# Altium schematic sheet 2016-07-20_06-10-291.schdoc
size 274 x 137 mm; SheetNumber: 1; SheetTotal: 1
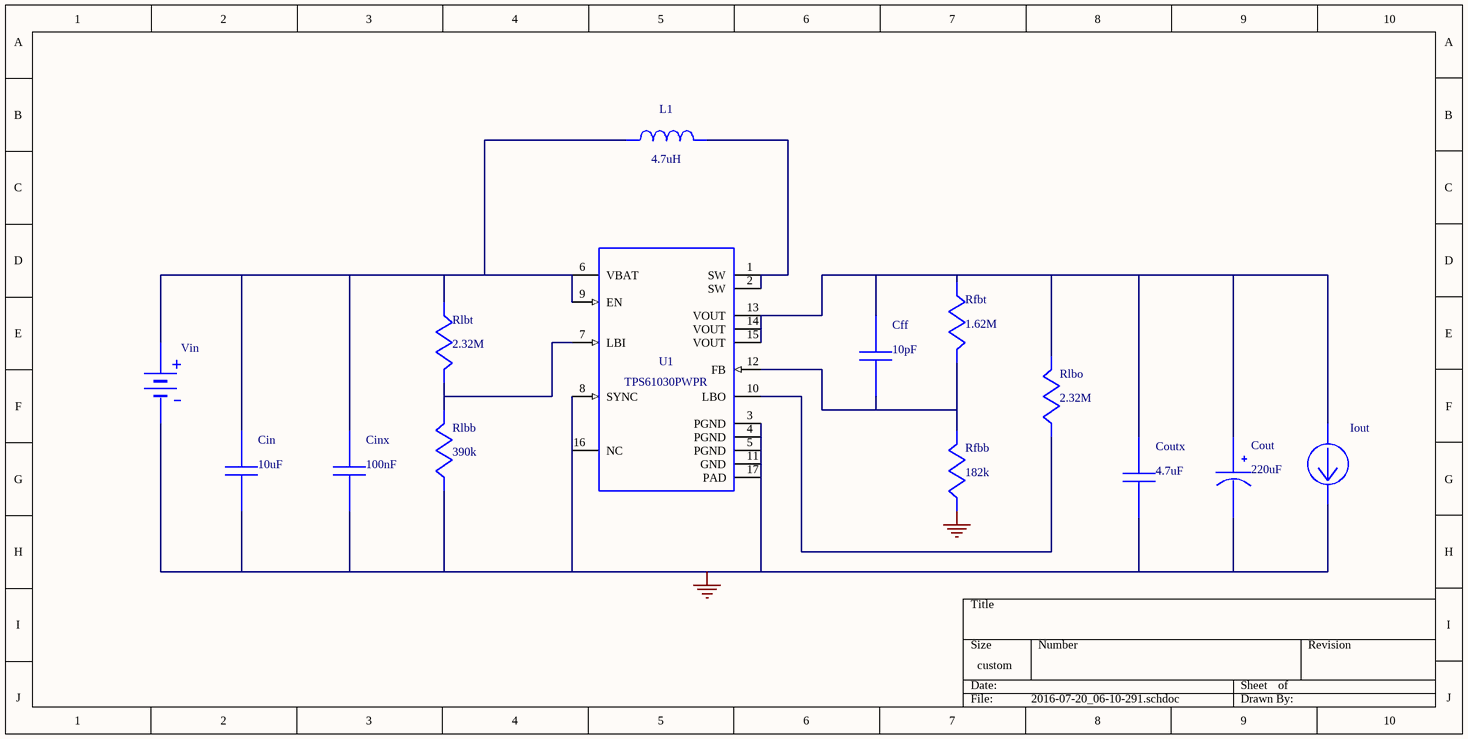
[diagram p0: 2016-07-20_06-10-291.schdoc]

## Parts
Cff  value 10pF  (hidden comment: C0805C100M4GACTU)
Cin  value 10uF  (hidden comment: GRM188R60J106ME47D)
Cinx  value 100nF  (hidden comment: GRM155R61A104KA01D)
Cout  value 220uF  (hidden comment: 6TPE220MAZB)
Coutx  value 4.7uF  (hidden comment: GRM188R60J475KE19D)
Iout  WB_CURRENT_LOAD  (value not drawn)
L1  value 4.7uH  (hidden comment: SRU1048-4R7Y)
Rfbb  value 182k  (hidden comment: CRCW0402182KFKED)
Rfbt  value 1.62M  (hidden comment: CRCW04021M62FKED)
Rlbb  value 390k  (hidden comment: RC0603FR-07390KL)
Rlbo  value 2.32M  (hidden comment: CRCW04022M32FKED)
Rlbt  value 2.32M  (hidden comment: CRCW04022M32FKED)
U1  TPS61030PWPR
Vin  WB_BATTERY  (value not drawn)

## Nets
0: Cin.2 Cinx.2 Cout.2(-) Coutx.2 Iout.2(-) Rfbb.2 Rlbb.2 U1.3(PGND) U1.4(PGND) U1.5(PGND) U1.8(SYNC) U1.11(GND) U1.16(NC) U1.17(PAD) Vin.2(-)
NetCff_1: Cff.1 Cout.1(+) Coutx.1 Iout.1(+) Rfbt.2 Rlbo.1 U1.13(VOUT) U1.14(VOUT) U1.15(VOUT)
NetCff_2: Cff.2 Rfbb.1 Rfbt.1 U1.12(FB)
NetCin_1: Cin.1 Cinx.1 L1.2 Rlbt.2 U1.6(VBAT) U1.9(EN) Vin.1(+)
NetL1_1: L1.1 U1.1(SW) U1.2(SW)
NetRlbb_1: Rlbb.1 Rlbt.1 U1.7(LBI)
NetRlbo_2: Rlbo.2 U1.10(LBO)

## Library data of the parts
Cff = C0805C100M4GACTU: Manufacturer Name: Kemet
Cin = GRM188R60J106ME47D: GRM188R60J106ME4; Manufacturer Name: MuRata
Cinx = GRM155R61A104KA01D: GRM155R61A104KA0; Manufacturer Name: MuRata
Cout = 6TPE220MAZB: Manufacturer Name: Panasonic
Coutx = GRM188R60J475KE19D: GRM188R60J475KE1; Manufacturer Name: MuRata
L1 = SRU1048-4R7Y: Manufacturer Name: Bourns
Rfbb = CRCW0402182KFKED: Manufacturer Name: Vishay-Dale
Rfbt = CRCW04021M62FKED: Manufacturer Name: Vishay-Dale
Rlbb = RC0603FR-07390KL: Manufacturer Name: Yageo America
Rlbo Rlbt = CRCW04022M32FKED: Manufacturer Name: Vishay-Dale
U1 = TPS61030PWPR: Manufacturer Name: Texas Instruments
